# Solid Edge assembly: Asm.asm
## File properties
Author: Deepak Maini
Template: Normal.asm
Last saved by: CADCIM
Revision: 4
Application: Solid Edge
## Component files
multi-2-plate.par
handle ball.par
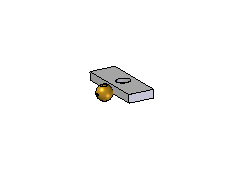
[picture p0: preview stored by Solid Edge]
